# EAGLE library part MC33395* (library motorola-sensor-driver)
BLDC Motor Control, Three-Phase Gate Driver IC Source: http://www.freescale.com/files/analog/doc/data_sheet/MC33395.pdf
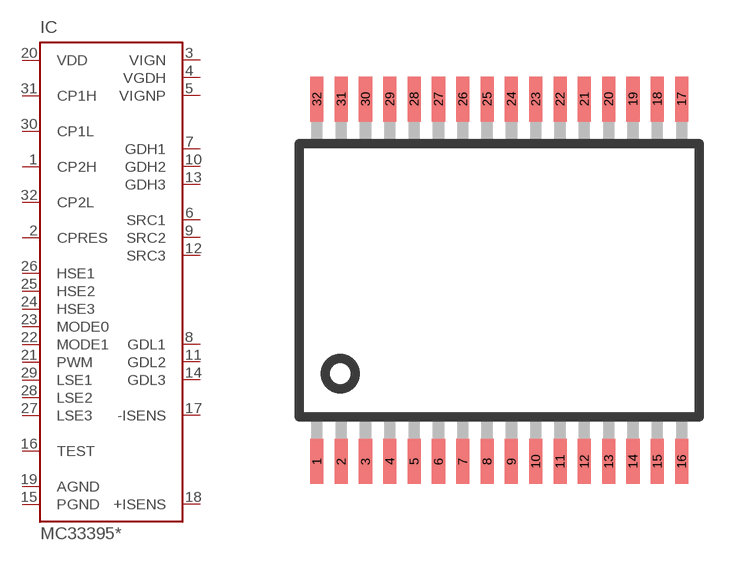
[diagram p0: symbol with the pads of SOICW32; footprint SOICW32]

Designator prefix IC

## MC33395DWB, MC33395TDWB  [SOICW32]
1  CP2H  pas
2  CPRES  pas
3  VIGN  pwr
4  VGDH  out
5  VIGNP  pas
6  SRC1  in
7  GDH1  out
8  GDL1  out
9  SRC2  in
10  GDH2  out
11  GDL2  out
12  SRC3  in
13  GDH3  out
14  GDL3  out
15  PGND  pwr
16  TEST  in
17  -ISENS  in
18  +ISENS  in
19  AGND  pwr
20  VDD  pwr
21  PWM  in
22  MODE1  in
23  MODE0  in
24  HSE3  in
25  HSE2  in
26  HSE1  in
27  LSE3  in
28  LSE2  in
29  LSE1  in
30  CP1L  pas
31  CP1H  pas
32  CP2L  pas

## Footprint SOICW32 (pad centres in mm)
Small Outline Package wide source www.motorola.com; BR1568.pdf
smd 0.35 x 1.2: 1 -4.875,-4.85; 2 -4.225,-4.85; 3 -3.575,-4.85; 4 -2.925,-4.85; 5 -2.275,-4.85; 6 -1.625,-4.85; 7 -0.975,-4.85; 8 -0.325,-4.85; 9 0.325,-4.85; 10 0.975,-4.85; 11 1.625,-4.85; 12 2.275,-4.85; 13 2.925,-4.85; 14 3.575,-4.85; 15 4.225,-4.85; 16 4.875,-4.85; 17 4.875,4.85; 18 4.225,4.85; 19 3.575,4.85; 20 2.925,4.85; 21 2.275,4.85; 22 1.625,4.85; 23 0.975,4.85; 24 0.325,4.85; 25 -0.325,4.85; 26 -0.975,4.85; 27 -1.625,4.85; 28 -2.275,4.85; 29 -2.925,4.85; 30 -3.575,4.85; 31 -4.225,4.85; 32 -4.875,4.85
